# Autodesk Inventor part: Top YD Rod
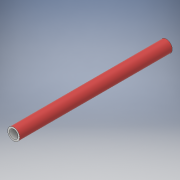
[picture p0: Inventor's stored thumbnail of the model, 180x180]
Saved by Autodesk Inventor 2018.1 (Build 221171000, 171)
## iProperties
Created: 2018-06
Part Number: Top YD Rod
Material: Generic
Document SubType Name: Modeling
Designer: Ryan
Density: 1 g/cm^3
Appearance: Default
Author: Ryan
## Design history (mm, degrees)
derived "Assembly3 Part out.iam"
sketch "Sketch1"
  geometry: L1 (-38.527, 77.015)-(136.232, 77.015); L2 (136.232, 77.015)-(136.232, -217.058); L3 (136.232, -217.058)-(-38.527, -217.058); L4 (-38.527, -217.058)-(-38.527, 77.015); 1 further point
  constraints: 8 end point, 2 parallel, 1 horizontal, 1 perpendicular
extrude "Extrusion1" cut sketch "Sketch1" distance "d1" = 25.4; taper "d2" = 0 deg
workplane "Work Plane2"
  workplane "Work Plane1"
workpoint "Work Point1"
workplane "Work Plane3"
workplane "Work Plane4"
workplane "Work Plane5"
workplane "Work Plane6"
workplane "Work Plane7"
workplane "Work Plane8"
workplane "Work Plane9"
workplane "Work Plane10"
workplane "Work Plane11"
workplane "Work Plane12"
sketch "Sketch2"
  geometry: L1 (-211.785, 45.946)-(135.217, 45.946); L2 (135.217, 45.946)-(135.217, -115.689); L3 (135.217, -115.689)-(-211.785, -115.689); L4 (-211.785, -115.689)-(-211.785, 45.946); 1 further point
  constraints: 8 end point, 2 parallel, 1 horizontal, 1 perpendicular
extrude "Extrusion2" cut sketch "Sketch2" distance "d10" = 160.3375; taper "d11" = 0 deg
sketch "Sketch3"
  geometry: L1 (176.508, 33.759)-(-69.152, 33.759); L2 (-69.152, 33.759)-(-69.152, -102.861); L3 (-69.152, -102.861)-(176.508, -102.861); L4 (176.508, -102.861)-(176.508, 33.759); 1 further point
  constraints: 8 end point, 2 parallel, 1 horizontal, 1 perpendicular
extrude "Extrusion3" cut sketch "Sketch3" distance "d12" = 160.3375; taper "d13" = 0 deg
sketch "Sketch4"
  geometry: L1 (-164.321, -12.422)-(63.379, -12.422); L2 (63.379, -12.422)-(63.379, -102.219); L3 (63.379, -102.219)-(-164.321, -102.219); L4 (-164.321, -102.219)-(-164.321, -12.422); L5 (-22.57, -91.957)-(-131.609, -91.957); L6 (-131.609, -91.957)-(-131.609, 20.931); L7 (-131.609, 20.931)-(-22.57, 20.931); L8 (-22.57, 20.931)-(-22.57, -91.957); 1 further point
  constraints: 16 end point, 4 parallel, 2 horizontal, 2 perpendicular
extrude "Extrusion4" cut sketch "Sketch4" distance "d14" = 160.3375; taper "d15" = 0 deg
sketch "Sketch5"
  geometry: C1 r 3.429 at (0, 0); 1 further point
  constraints: 1 centre point
  dimensions: "d16" = 6.858 diameter of C1
extrude "Extrusion5" cut sketch "Sketch5" distance "d17" = 12.7; taper "d18" = 0 deg
sketch "Sketch6"
  geometry: C1 r 3.429 at (0, 0); 1 further point
  constraints: 1 centre point
  dimensions: "d19" = 6.858 diameter of C1
extrude "Extrusion6" cut sketch "Sketch6" distance "d20" = 12.7; taper "d21" = 0 deg
body "Solid1"
node "Rov v4.2.ipt:1" dims "d0" = 10
node "Motor mount.ipt:1" dims "d0" = 10
node "Motor mount.ipt:2" dims "d0" = 10
node "Motor mount_MIR2.ipt:1" dims "d0" = 10
other parameters: "d3" = 6.35, "d4" = 12.7, "d5" = -12.7, "d6" = 12.7, "d7" = -12.7, "d8" = 6.35, "d9" = -6.35
